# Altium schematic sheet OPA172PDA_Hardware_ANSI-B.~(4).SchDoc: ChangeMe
size 431 x 279 mm; Date: Not shown in title block; ApprovedBy: Not shown in title block; CheckedBy: Not shown in title block; Author: Not shown in title block; CompanyName: Not shown in title block; DrawnBy: Enter Full Name; Engineer: Not shown in title block; Organization: Not shown in title block; Address1: Not shown in title block; Address2: Not shown in title block; Address3: Not shown in title block; Address4: Not shown in title block; DocumentNumber: 3; Revision: Use project parameter SCH_Rev; SheetNumber: 3; SheetTotal: 3; PageSetup: Record=PageOptions|CenterHorizontal=True|CenterVertical=True|PrintScale=1.00|XCorrection=1.00|YCorrection=1.00|PrintKind=0|BorderSize=5000000|LeftOffset=0|BottomOffset=0|Orientation=2|PaperLength=1000|PaperWidth=1000|Scale=100|PaperSource=15|PrintQuality=600|MediaType=1|DitherType=10|PaperKind=Letter|PrintScaleMode=1
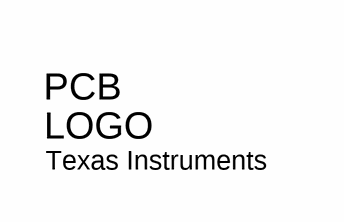
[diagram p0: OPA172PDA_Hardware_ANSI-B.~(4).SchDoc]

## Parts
Logo1  Texas Instruments  [TI_Stacked_Overlay_Small]  (no BOM)

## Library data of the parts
Logo1 = TI_Logo: Texas Instrument Corporate Signature; SymbolCreator: codlsc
